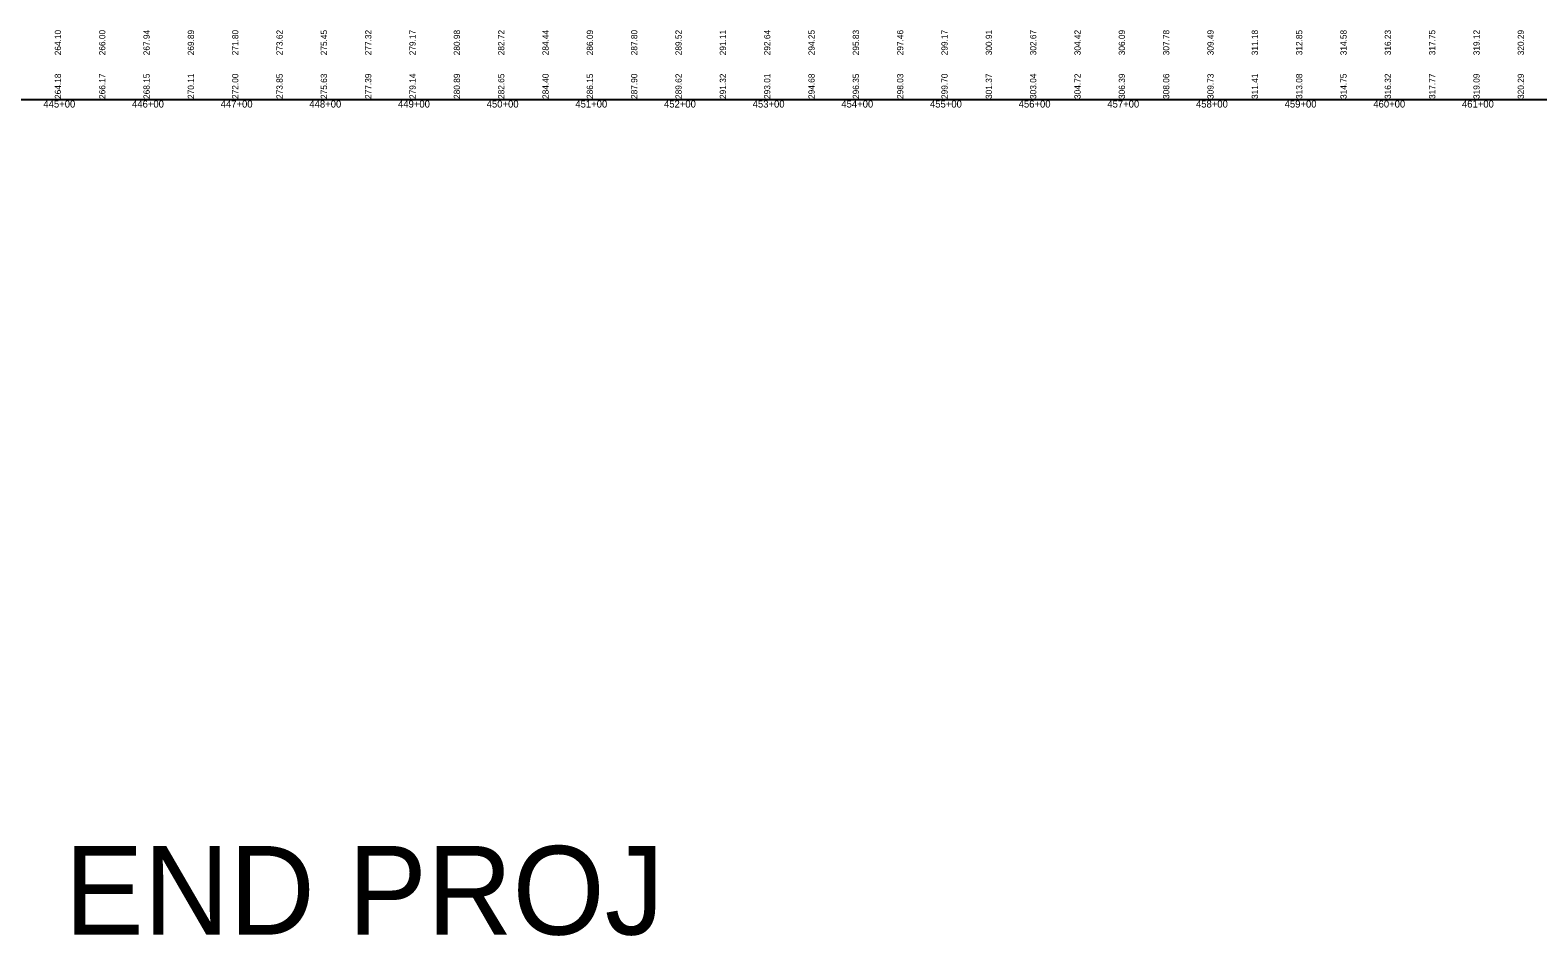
# Model space of a CAD drawing. Extents: x 1876258 to 1932803, y 754739 to 837911.
# Drawn here: x 1922827 to 1924528, y 829561 to 830583 of the extents above; entities that cross this region are included whole.
import ezdxf

# ---------------------------------------------------------------- set-up
doc = ezdxf.new("R2010")
doc.units = 0
for name, color, linetype in [('RD_DDB_StaTX', 7, 'Continuous'), ('RD_DDB_StripGrade', 7, 'Continuous'), ('RD_GPK_Profile_Cell', 7, 'Continuous'), ('RD_Sketch1', 7, 'Continuous')]:
    doc.layers.add(name, color=color, linetype=linetype)

msp = doc.modelspace()

# ---------------------------------------------------------------- linework, layer by layer
at = {"layer": 'RD_GPK_Profile_Cell'}
msp.add_line((1878363.1, 830504.3), (1926563.1, 830504.3), dxfattribs=at)

# ---------------------------------------------------------------- texts
at = {"layer": 'RD_DDB_StaTX'}
for s, p in [('445+00', (1922842.2, 830495.3)), ('445+00', (1922842.2, 830495.3)), ('446+00', (1922942.2, 830495.3)), ('446+00', (1922942.2, 830495.3)), ('447+00', (1923042.2, 830495.3)), ('447+00', (1923042.2, 830495.3)), ('448+00', (1923142.2, 830495.3)), ('448+00', (1923142.2, 830495.3)), ('449+00', (1923242.2, 830495.3)), ('449+00', (1923242.2, 830495.3)), ('450+00', (1923342.2, 830495.3)), ('450+00', (1923342.2, 830495.3)), ('451+00', (1923442.2, 830495.3)), ('451+00', (1923442.2, 830495.3)), ('452+00', (1923542.2, 830495.3)), ('452+00', (1923542.2, 830495.3)), ('453+00', (1923642.2, 830495.3)), ('453+00', (1923642.2, 830495.3)), ('454+00', (1923742.2, 830495.3)), ('454+00', (1923742.2, 830495.3)), ('455+00', (1923842.2, 830495.3)), ('455+00', (1923842.2, 830495.3)), ('456+00', (1923942.2, 830495.3)), ('456+00', (1923942.2, 830495.3)), ('457+00', (1924042.2, 830495.3)), ('457+00', (1924042.2, 830495.3)), ('458+00', (1924142.2, 830495.3)), ('458+00', (1924142.2, 830495.3)), ('459+00', (1924242.2, 830495.3)), ('459+00', (1924242.2, 830495.3)), ('460+00', (1924342.2, 830495.3)), ('460+00', (1924342.2, 830495.3)), ('461+00', (1924442.2, 830495.3)), ('461+00', (1924442.2, 830495.3))]:
    msp.add_text(s, height=8, dxfattribs=at).set_placement(p)
at = {"layer": 'RD_DDB_StripGrade'}
for s, p in [('264.10', (1922862.1, 830554.3)), ('266.00', (1922912.1, 830554.3)), ('267.94', (1922962.1, 830554.3)), ('269.89', (1923012.1, 830554.3)), ('271.80', (1923062.1, 830554.3)), ('273.62', (1923112.1, 830554.3)), ('275.45', (1923162.1, 830554.3)), ('277.32', (1923212.1, 830554.3)), ('279.17', (1923262.1, 830554.3)), ('280.98', (1923312.1, 830554.3)), ('282.72', (1923362.1, 830554.3)), ('284.44', (1923412.1, 830554.3)), ('286.09', (1923462.1, 830554.3)), ('287.80', (1923512.1, 830554.3)), ('289.52', (1923562.1, 830554.3)), ('291.11', (1923612.1, 830554.3)), ('292.64', (1923662.1, 830554.3)), ('294.25', (1923712.1, 830554.3)), ('295.83', (1923762.1, 830554.3)), ('297.46', (1923812.1, 830554.3)), ('299.17', (1923862.1, 830554.3)), ('300.91', (1923912.1, 830554.3)), ('302.67', (1923962.1, 830554.3)), ('304.42', (1924012.1, 830554.3)), ('306.09', (1924062.1, 830554.3)), ('307.78', (1924112.1, 830554.3)), ('309.49', (1924162.1, 830554.3)), ('311.18', (1924212.1, 830554.3)), ('312.85', (1924262.1, 830554.3)), ('314.58', (1924312.1, 830554.3)), ('316.23', (1924362.1, 830554.3)), ('317.75', (1924412.1, 830554.3)), ('319.12', (1924462.1, 830554.3)), ('320.29', (1924512.1, 830554.3)), ('264.18', (1922862.1, 830505)), ('266.17', (1922912.1, 830505)), ('268.15', (1922962.1, 830505)), ('270.11', (1923012.1, 830505)), ('272.00', (1923062.1, 830505)), ('273.85', (1923112.1, 830505)), ('275.63', (1923162.1, 830505)), ('277.39', (1923212.1, 830505)), ('279.14', (1923262.1, 830505)), ('280.89', (1923312.1, 830505)), ('282.65', (1923362.1, 830505)), ('284.40', (1923412.1, 830505)), ('286.15', (1923462.1, 830505)), ('287.90', (1923512.1, 830505)), ('289.62', (1923562.1, 830505)), ('291.32', (1923612.1, 830505)), ('293.01', (1923662.1, 830505)), ('294.68', (1923712.1, 830505)), ('296.35', (1923762.1, 830505)), ('298.03', (1923812.1, 830505)), ('299.70', (1923862.1, 830505)), ('301.37', (1923912.1, 830505)), ('303.04', (1923962.1, 830505)), ('304.72', (1924012.1, 830505)), ('306.39', (1924062.1, 830505)), ('308.06', (1924112.1, 830505)), ('309.73', (1924162.1, 830505)), ('311.41', (1924212.1, 830505)), ('313.08', (1924262.1, 830505)), ('314.75', (1924312.1, 830505)), ('316.32', (1924362.1, 830505)), ('317.77', (1924412.1, 830505)), ('319.09', (1924462.1, 830505)), ('320.29', (1924512.1, 830505))]:
    msp.add_text(s, height=7, rotation=90, dxfattribs=at).set_placement(p)
at = {"layer": 'RD_Sketch1'}
msp.add_text('END PROJ', height=100, dxfattribs=at).set_placement((1922866.1, 829562))

doc.saveas('drawing.dxf')
